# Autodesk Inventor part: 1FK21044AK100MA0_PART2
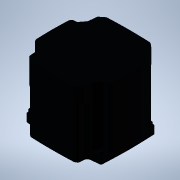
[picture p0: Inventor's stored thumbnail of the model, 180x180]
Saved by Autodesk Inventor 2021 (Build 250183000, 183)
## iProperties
Created: 2025-04
Part Number: 1FK21044AK100MA0_PART2
Material: Generic
Catalog Web Link: www.3dfindit.com
Description: -Servo synchronous motor
Document SubType Name: Modeling
Designer: psAdmin
Mass: 372.123 g
Surface Area: 313.117 cm^2
Volume: 372.123 cm^3
Density: 1 g/cm^3
Appearance: PSOLRGB-38-46-56
Category: PARTsolutions
Title: 1FK21044AK100MA0_PART2
Author: Cadenas PARTsolutions
Comments: Servo synchronous motor
Sending System: PARTsolutions
Preprocessor: ST-DEVELOPER v19.3
PSOL_IDENT_0: {$CADENAS_DATA/23d-libs/siemens_ag/_cat_/5e/d8/1fk21044ak100ma0.prj},213 {VTYP=3D},{NB=1FK21044AK100
PSOL_IDENT_1: MA0_PART2},{LINA=1FK21044AK100MA0_PART2},{NN=1FK21044AK100MA0_PART2},{NOPRJ=TRUE},{DATE=19.08.2025 1
PSOL_IDENT_2: 4:00:41},{GEOMDATE=30.07.2025 02:00:53},{VERSION=},{LINEID=10},{WBVAR=},{WBNUMERIC=}  {NB=1FK21044AK
PSOL_IDENT_3: 100MA0_PART2},{LINA=1FK21044AK100MA0_PART2},{KT=DUMMY},{PREVIEW=../../../_pool_/cb/72/p_d211_xx_0043
PSOL_IDENT_4: 4j.png},{DESCSHORT=SIMOTICS S-1FK2 HD, SINAMICS S210 3AC 400V-480V, 0.95 Nm, 6000 rpm},{DESCLONG=SIM
PSOL_IDENT_5: OTICS S-1FK2 HD servo motor M0=1.27 Nm; PN = 0.6 kW at nN=6000 rpm (380-480 V); PN = 0.4 kW at nN=30
PSOL_IDENT_6: 00 rpm (200-240 V); with holding brake; degree of protection IP64; cylindrical shaft D19x40mm; absol
PSOL_IDENT_7: ute encoder 22-bit + 12-bit multiturn (encoder AM22DQC); with OCC interface; plug size M17, rotatabl
PSOL_IDENT_8: e; SIMOTICS S-1FK2 servomotorfor a wide range of uses in industrial environments. SIMOTICS S‑1FK2 se
PSOL_IDENT_9: rvomotors are compact synchronous motors with a high dynamic performance that set themselves apart a
PSOL_IDENT_10: s a result of their high power density, degree of protection and overload capability. The motors are
PSOL_IDENT_11: available in two variants: as High Dynamic variant (highest dynamic performance as a result of the
PSOL_IDENT_12: low intrinsic moment of inertia for applications demanding a high dynamic performance with low moved
PSOL_IDENT_13: masses) - and as Compact variant (precise and stable closed-loop control for medium up to large mov
PSOL_IDENT_14: ed masses as a result of a medium intrinsic moment of inertia). SIMOTICSS‑1FK2 servomotors fully exp
PSOL_IDENT_15: loit their strengths in a system with the SINAMICSS210 frequency converter and simple connection usi
PSOL_IDENT_16: ng the one cable connection (OCC). Advantages include the short control and positioning times, fast
PSOL_IDENT_17: and precise correction of disturbing quantities as well as stable control with a high dynamic perfor
PSOL_IDENT_18: mance. The servo motors can be configured to address a wide range of requirements. For example with
PSOL_IDENT_19: and without holding brake, IP64 or IP65 degree of protection, singleturn or multiturn absolute encod
PSOL_IDENT_20: ers - to name just a few. Further, the servomotors are available in different shaft heights extendin
PSOL_IDENT_21: g from 20 to 100. A shaft sealing ring is available to achieve an IP65 degree of protection and for
PSOL_IDENT_22: subsequent mounting at the motor or as spare part. SIMOTICS - the optimum motor for each and every m
PSOL_IDENT_23: otion control application.},{INTNO=804766910005},{SUPPLIERALTNO=1FK2104-4AK10-0MA0},{MANUID=1FK21044
PSOL_IDENT_24: AK100MA0},{MANUNAME=Siemens},{MANUTYPEDESC=Synchronous motor 1FK2-HD 1,27 Nm},{AAU732=SIMOTICS},{AAO
PSOL_IDENT_25: 057=S-1FK2},{AAU734=SIMOTICS S-1FK2 HD servo motor M0=1.27 Nm; PN = 0.6 kW at nN=6000 rpm (380-480 V
PSOL_IDENT_26: ); PN = 0.4 kW at nN=3000 rpm (200-240 V); with holding brake; degree of protection IP64; cylindrica
PSOL_IDENT_27: l shaft D19x40mm; absolute encoder 22-bit + 12-bit multiturn (encoder AM22DQC); with OCC interface;
PSOL_IDENT_28: plug size M17, rotatable;},{AAW338=Synchronous motor 1FK2-HD 1,27 Nm},{AAO742=SIMOTICS},{AAO663=4042
PSOL_IDENT_29: 948691076},{NOCUPEROU=1},{PRICEQUANTITY=1},{QUANTITYMIN=1},{QUANTITYINT=1},{CTN=85015100},{COO=DE},{
PSOL_IDENT_30: AAO676=1FK2104-4AK10-0MA0},{AAO677=Siemens AG},{ORDERUNIT=C62},{CONTENTUNIT=C62}
NB: 1FK21044AK100MA0_PART2
NT: Servo synchronous motor
NBSYN: $MANUID._PART2
LINA: 1FK21044AK100MA0_PART2
CATALOG: SIEMENS
PREVIEW: ../../../_pool_/cb/72/p_d211_xx_00434j.png
DESCSHORT: SIMOTICS S-1FK2 HD, SINAMICS S210 3AC 400V-480V, 0.95 Nm, 6000 rpm
DESCLONG: SIMOTICS S-1FK2 HD servo motor M0=1.27 Nm; PN = 0.6 kW at nN=6000 rpm (380-480 V); PN = 0.4 kW at nN=3000 rpm (200-240 V); with holding brake; degree of protect
INTNO: 804766910005
SUPPLIERALTNO: 1FK2104-4AK10-0MA0
MANUID: 1FK21044AK100MA0
MANUNAME: Siemens
MANUTYPEDESC: Synchronous motor 1FK2-HD 1,27 Nm
AAU732: SIMOTICS
AAO057: S-1FK2
AAU734: SIMOTICS S-1FK2 HD servo motor M0=1.27 Nm; PN = 0.6 kW at nN=6000 rpm (380-480 V); PN = 0.4 kW at nN=3000 rpm (200-240 V); with holding brake; degree of protect
AAW338: Synchronous motor 1FK2-HD 1,27 Nm
AAO742: SIMOTICS
AAO663: 4042948691076.0
NOCUPEROU: 1
PRICEQUANTITY: 1
QUANTITYMIN: 1
QUANTITYINT: 1
CTN: 85015100
COO: DE
ARTICLENO: 1FK21044AK100MA0_PART2
BOMINFO: 1FK21044AK100MA0_PART2
CREATOR: CADENAS GmbH
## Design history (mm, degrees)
feature "2025_04_17_15_35_41_0843"
body "Solid1"
